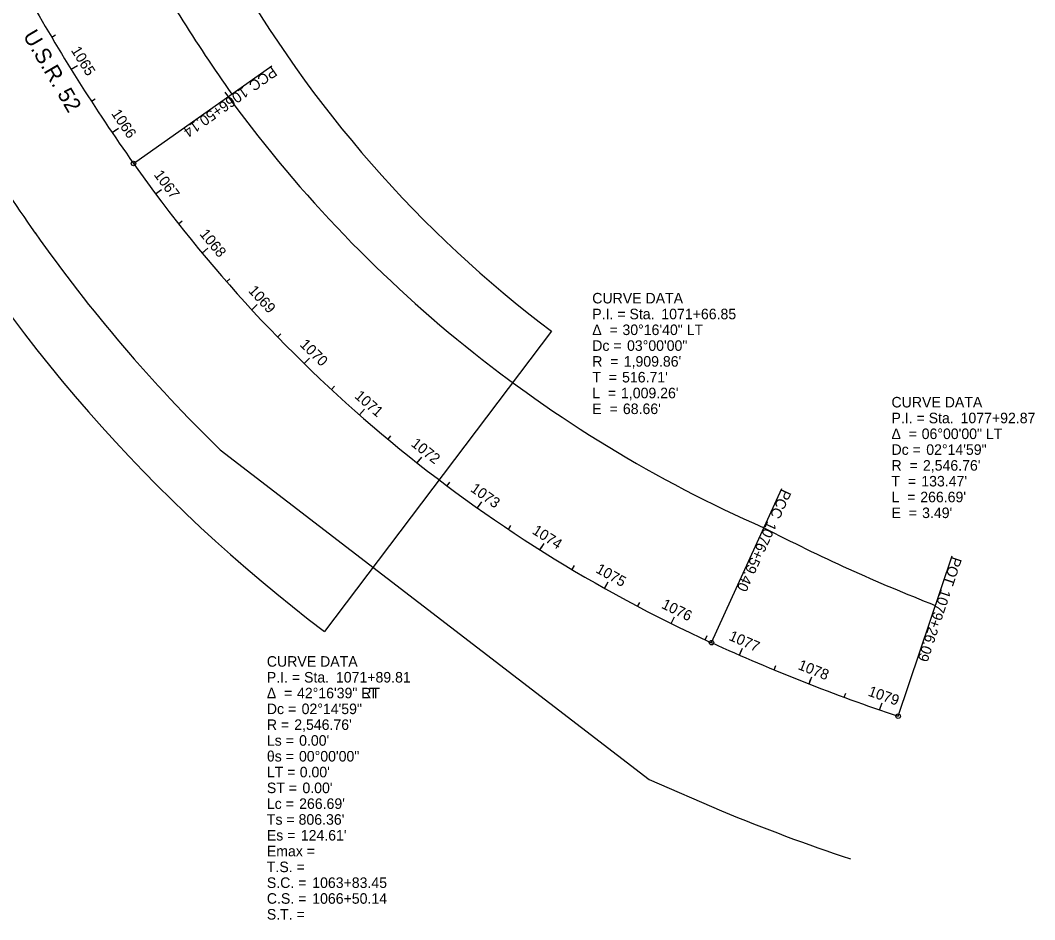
# Model space of a CAD drawing. Extents: x 1947854 to 1951648, y 150068 to 154534.
# Drawn here: x 1948658 to 1950006, y 151140 to 152335 of the extents above; entities that cross this region are included whole.
import ezdxf

# ---------------------------------------------------------------- set-up
doc = ezdxf.new("R2010")
doc.units = 0
for name, color, linetype in [('DR_X_Cells', 7, 'Continuous'), ('DR_X_Elev_Flow', 7, 'Continuous'), ('GE_X_Alignment', 7, 'Continuous'), ('GE_X_Alignment_100_Curve_Data', 7, 'Continuous'), ('RW_X_Esmt_LA', 7, 'Continuous'), ('SC_Scratch1', 7, 'Continuous'), ('SN_X_Public', 7, 'Continuous'), ('SV_P_Control_Cells_Set', 7, 'Continuous'), ('SV_X_Random_Point', 7, 'Continuous')]:
    doc.layers.add(name, color=color, linetype=linetype)

msp = doc.modelspace()

# ---------------------------------------------------------------- linework, layer by layer
at = {"layer": 'DR_X_Elev_Flow'}
for p, q in [((1948725.4, 152270.2), (1948730.5, 152273.3)), ((1948808.3, 152145), (1948992.2, 152274.7)), ((1949035, 151879.1), (1949042, 151886.3)), ((1949576.3, 151508.4), (1949669.7, 151713.1)), ((1949824.3, 151410.6), (1949895.8, 151623.9)), ((1949434.2, 151580.5), (1949437.2, 151585.7))]:
    msp.add_line(p, q, dxfattribs=at)
for centre in [(1948808.3, 152145), (1949576.3, 151508.4), (1949824.3, 151410.6)]:
    msp.add_circle(centre, 3, dxfattribs=at)
at = {"layer": 'GE_X_Alignment'}
for centre, radius, start, end in [((1950889.3, 153613.1), 2546.8, 209.2034, 215.2032), ((1950368.9, 153246), 1909.9, 215.2032, 245.481), ((1950633.2, 153825.5), 2546.8, 245.481, 251.4809)]:
    msp.add_arc(centre, radius, start, end, dxfattribs=at)
at = {"layer": 'RW_X_Esmt_LA'}
for p, q in [((1948923.3, 151764.6), (1949493.3, 151326.4)), ((1949493.3, 151326.4), (1949589.5, 151284.7))]:
    msp.add_line(p, q, dxfattribs=at)
for centre, radius, start, end in [((1950889.3, 153613.1), 2386.8, 209.2034, 215.2032), ((1950889.3, 153613.1), 2706.8, 209.2034, 215.2032), ((1950349, 153263.5), 1749.9, 215.7927, 246.3078), ((1950368.9, 153246), 2069.9, 215.2032, 225.699), ((1950743.9, 153780.3), 2386.8, 242.6106, 248.6111), ((1950633.2, 153825.5), 2746.8, 247.6673, 251.4809)]:
    msp.add_arc(centre, radius, start, end, dxfattribs=at)
at = {"layer": 'SC_Scratch1'}
msp.add_line((1949363.5, 151922.1), (1949061.9, 151523.3), dxfattribs=at)
for radius in [1600, 2100]:
    msp.add_arc((1950328.6, 153198.2), radius, 209.4864, 232.9007, dxfattribs=at)
at = {"layer": 'SN_X_Public'}
for p, q in [((1948699.5, 152312.9), (1948704.7, 152316)), ((1948725.4, 152270.2), (1948733.9, 152275.4)), ((1948808.3, 152145), (1948992.2, 152274.7)), ((1948752.2, 152227.9), (1948757.3, 152231.2)), ((1948779.8, 152186.2), (1948788.1, 152191.9)), ((1948808.3, 152145.1), (1948813.2, 152148.6)), ((1948837.6, 152104.6), (1948845.6, 152110.6)), ((1948868, 152064.9), (1948872.7, 152068.7)), ((1948899.4, 152026.1), (1948907.1, 152032.4)), ((1948931.9, 151988), (1948936.4, 151992)), ((1948965.3, 151950.8), (1948972.6, 151957.6)), ((1948999.7, 151914.5), (1949004, 151918.7)), ((1949035, 151879.1), (1949042, 151886.3)), ((1949071.2, 151844.7), (1949075.3, 151849.1)), ((1949108.4, 151811.2), (1949115, 151818.7)), ((1949146.4, 151778.7), (1949150.2, 151783.3)), ((1949185.2, 151747.2), (1949191.4, 151755)), ((1949224.8, 151716.7), (1949228.4, 151721.5)), ((1949576.3, 151508.4), (1949669.7, 151713.1)), ((1949265.2, 151687.3), (1949271, 151695.5)), ((1949306.4, 151658.9), (1949309.8, 151663.9)), ((1949348.3, 151631.7), (1949353.7, 151640.1)), ((1949824.3, 151410.6), (1949895.8, 151623.9)), ((1949390.9, 151605.5), (1949394, 151610.7)), ((1949434.2, 151580.5), (1949439.1, 151589.2)), ((1949478.1, 151556.6), (1949480.9, 151561.9)), ((1949522.7, 151533.8), (1949527.1, 151542.8)), ((1949567.8, 151512.3), (1949570.3, 151517.7)), ((1949613.4, 151491.8), (1949617.4, 151501)), ((1949659.4, 151472.2), (1949661.7, 151477.8)), ((1949705.8, 151453.6), (1949709.4, 151462.9)), ((1949752.5, 151435.8), (1949754.6, 151441.4)), ((1949799.6, 151419), (1949802.9, 151428.4))]:
    msp.add_line(p, q, dxfattribs=at)
for centre in [(1948808.3, 152145), (1949576.3, 151508.4), (1949824.3, 151410.6)]:
    msp.add_circle(centre, 3, dxfattribs=at)
at = {"layer": 'SV_X_Random_Point'}
for p, q in [((1948725.4, 152270.2), (1948733.9, 152275.4)), ((1948808.3, 152145), (1948992.2, 152274.7)), ((1948779.8, 152186.2), (1948784.8, 152189.6)), ((1948837.6, 152104.6), (1948842.4, 152108.2)), ((1948899.4, 152026.1), (1948904.1, 152029.9)), ((1948965.3, 151950.8), (1948969.7, 151954.9)), ((1949035, 151879.1), (1949042, 151886.3)), ((1949108.4, 151811.2), (1949112.3, 151815.7)), ((1949185.2, 151747.2), (1949188.9, 151751.9)), ((1949576.3, 151508.4), (1949669.7, 151713.1)), ((1949265.2, 151687.3), (1949268.7, 151692.2)), ((1949348.3, 151631.7), (1949351.5, 151636.7)), ((1949824.3, 151410.6), (1949895.8, 151623.9)), ((1949434.2, 151580.5), (1949439.1, 151589.2)), ((1949522.7, 151533.8), (1949525.3, 151539.2)), ((1949613.4, 151491.8), (1949615.8, 151497.3)), ((1949705.8, 151453.6), (1949708, 151459.2)), ((1949799.6, 151419), (1949801.6, 151424.7))]:
    msp.add_line(p, q, dxfattribs=at)
for centre in [(1948808.3, 152145), (1949576.3, 151508.4), (1949824.3, 151410.6)]:
    msp.add_circle(centre, 3, dxfattribs=at)

# ---------------------------------------------------------------- texts
at = {"layer": 'DR_X_Cells'}
for s, p in [('CURVE DATA', (1949417.8, 151959.1)), ('P.I. = Sta. ', (1949417.8, 151938.1)), ('1071+66.85', (1949509.6, 151938.1)), ('Δ  = ', (1949417.8, 151917.1)), ('30°16\'40" LT', (1949457.9, 151917.1)), ('Dc = ', (1949417.8, 151896.1)), ('03°00\'00"', (1949464, 151896.1)), ('R  = ', (1949417.8, 151875.1)), ("1,909.86'", (1949459.6, 151875.1)), ('T  = ', (1949417.8, 151854.1)), ("516.71'", (1949457.4, 151854.1)), ('L  = ', (1949417.8, 151833.1)), ("1,009.26'", (1949456, 151833.1)), ('CURVE DATA', (1949815.4, 151820.9)), ('E  = ', (1949417.8, 151812.1)), ("68.66'", (1949458.5, 151812.1)), ('P.I. = Sta. ', (1949815.4, 151799.9)), ('1077+92.87', (1949907.2, 151799.9)), ('Δ  = ', (1949815.4, 151778.9)), ('06°00\'00" LT', (1949855.5, 151778.9)), ('Dc = ', (1949815.4, 151757.9)), ('02°14\'59"', (1949861.6, 151757.9)), ('R  = ', (1949815.4, 151736.9)), ("2,546.76'", (1949857.2, 151736.9)), ('T  = ', (1949815.4, 151715.9)), ("133.47'", (1949855, 151715.9)), ('L  = ', (1949815.4, 151694.9)), ("266.69'", (1949853.6, 151694.9)), ('E  = ', (1949815.4, 151673.9)), ("3.49'", (1949856.1, 151673.9)), ('CURVE DATA', (1948985.4, 151476.4)), ('CURVE DATA', (1948985.4, 151476.4)), ('P.I. = Sta. ', (1948985.4, 151455.4)), ('P.I. = Sta. ', (1948985.4, 151455.4)), ('1071+89.81', (1949077.2, 151455.4)), ('1071+89.81', (1949077.2, 151455.4)), ('Δ  = ', (1948985.4, 151434.4)), ('Δ  = ', (1948985.4, 151434.4)), ('42°16\'39" LT', (1949025.5, 151434.4)), ('42°16\'39" RT', (1949025.5, 151434.4)), ('Dc = ', (1948985.4, 151413.4)), ('Dc = ', (1948985.4, 151413.4)), ('02°14\'59"', (1949031.6, 151413.4)), ('02°14\'59"', (1949031.6, 151413.4)), ('R = ', (1948985.4, 151392.4)), ('R = ', (1948985.4, 151392.4)), ("2,546.76'", (1949021.8, 151392.4)), ("2,546.76'", (1949021.8, 151392.4)), ('Ls = ', (1948985.4, 151371.4)), ('Ls = ', (1948985.4, 151371.4)), ("0.00'", (1949028.3, 151371.4)), ("0.00'", (1949028.3, 151371.4)), ('θs = ', (1948985.4, 151350.4)), ('θs = ', (1948985.4, 151350.4)), ('00°00\'00"', (1949028.1, 151350.4)), ('00°00\'00"', (1949028.1, 151350.4)), ('LT = ', (1948985.4, 151329.4)), ('LT = ', (1948985.4, 151329.4)), ("0.00'", (1949029.1, 151329.4)), ("0.00'", (1949029.1, 151329.4)), ('ST = ', (1948985.4, 151308.4)), ('ST = ', (1948985.4, 151308.4)), ("0.00'", (1949032.7, 151308.4)), ("0.00'", (1949032.7, 151308.4)), ('Lc = ', (1948985.4, 151287.4)), ('Lc = ', (1948985.4, 151287.4)), ("266.69'", (1949028.3, 151287.4)), ("266.69'", (1949028.3, 151287.4)), ('Ts = ', (1948985.4, 151266.4)), ('Ts = ', (1948985.4, 151266.4)), ("806.36'", (1949027.6, 151266.4)), ("806.36'", (1949027.6, 151266.4)), ('Es = ', (1948985.4, 151245.4)), ('Es = ', (1948985.4, 151245.4)), ("124.61'", (1949030.5, 151245.4)), ("124.61'", (1949030.5, 151245.4)), ('Emax = ', (1948985.4, 151224.4)), ('Emax = ', (1948985.4, 151224.4)), ('T.S. = ', (1948985.4, 151203.4)), ('T.S. = ', (1948985.4, 151203.4)), ('S.C. = ', (1948985.4, 151182.4)), ('S.C. = ', (1948985.4, 151182.4)), ('1063+83.45', (1949045.7, 151182.4)), ('1063+83.45', (1949045.7, 151182.4)), ('C.S. = ', (1948985.4, 151161.4)), ('C.S. = ', (1948985.4, 151161.4)), ('1066+50.14', (1949045.7, 151161.4)), ('1066+50.14', (1949045.7, 151161.4)), ('S.T. = ', (1948985.4, 151140.4)), ('S.T. = ', (1948985.4, 151140.4))]:
    msp.add_text(s, height=14, dxfattribs=at).set_placement(p)
at = {"layer": 'DR_X_Elev_Flow'}
for s, rotation, p in [('PCC', 215.2032, (1948992.5, 152274.6)), ('1066+50.14', 215.2032, (1948954.3, 152247.7)), ('1070', 315.699, (1949028.3, 151903.5)), ('PCC', 245.481, (1949670.1, 151713.3)), ('1076+59.40', 245.481, (1949650.7, 151670.8)), ('POT', 251.4809, (1949895.9, 151623.6)), ('1079+26.09', 251.4809, (1949881.4, 151580.3))]:
    msp.add_text(s, height=14, rotation=rotation, dxfattribs=at).set_placement(p)
at = {"layer": 'GE_X_Alignment_100_Curve_Data'}
for s, p in [('CURVE DATA', (1949417.8, 151959.1)), ('P.I. = Sta. ', (1949417.8, 151938.1)), ('1071+66.85', (1949509.6, 151938.1)), ('Δ  = ', (1949417.8, 151917.1)), ('30°16\'40" LT', (1949457.9, 151917.1)), ('Dc = ', (1949417.8, 151896.1)), ('03°00\'00"', (1949464, 151896.1)), ('R  = ', (1949417.8, 151875.1)), ("1,909.86'", (1949459.6, 151875.1)), ('T  = ', (1949417.8, 151854.1)), ("516.71'", (1949457.4, 151854.1)), ('L  = ', (1949417.8, 151833.1)), ("1,009.26'", (1949456, 151833.1)), ('CURVE DATA', (1949815.4, 151820.9)), ('E  = ', (1949417.8, 151812.1)), ("68.66'", (1949458.5, 151812.1)), ('P.I. = Sta. ', (1949815.4, 151799.9)), ('1077+92.87', (1949907.2, 151799.9)), ('Δ  = ', (1949815.4, 151778.9)), ('06°00\'00" LT', (1949855.5, 151778.9)), ('Dc = ', (1949815.4, 151757.9)), ('02°14\'59"', (1949861.6, 151757.9)), ('R  = ', (1949815.4, 151736.9)), ("2,546.76'", (1949857.2, 151736.9)), ('T  = ', (1949815.4, 151715.9)), ("133.47'", (1949855, 151715.9)), ('L  = ', (1949815.4, 151694.9)), ("266.69'", (1949853.6, 151694.9)), ('E  = ', (1949815.4, 151673.9)), ("3.49'", (1949856.1, 151673.9)), ('CURVE DATA', (1948985.4, 151476.4)), ('CURVE DATA', (1948985.4, 151476.4)), ('P.I. = Sta. ', (1948985.4, 151455.4)), ('P.I. = Sta. ', (1948985.4, 151455.4)), ('1071+89.81', (1949077.2, 151455.4)), ('1071+89.81', (1949077.2, 151455.4)), ('Δ  = ', (1948985.4, 151434.4)), ('Δ  = ', (1948985.4, 151434.4)), ('42°16\'39" LT', (1949025.5, 151434.4)), ('42°16\'39" RT', (1949025.5, 151434.4)), ('Dc = ', (1948985.4, 151413.4)), ('Dc = ', (1948985.4, 151413.4)), ('02°14\'59"', (1949031.6, 151413.4)), ('02°14\'59"', (1949031.6, 151413.4)), ('R = ', (1948985.4, 151392.4)), ('R = ', (1948985.4, 151392.4)), ("2,546.76'", (1949021.8, 151392.4)), ("2,546.76'", (1949021.8, 151392.4)), ('Ls = ', (1948985.4, 151371.4)), ('Ls = ', (1948985.4, 151371.4)), ("0.00'", (1949028.3, 151371.4)), ("0.00'", (1949028.3, 151371.4)), ('θs = ', (1948985.4, 151350.4)), ('θs = ', (1948985.4, 151350.4)), ('00°00\'00"', (1949028.1, 151350.4)), ('00°00\'00"', (1949028.1, 151350.4)), ('LT = ', (1948985.4, 151329.4)), ('LT = ', (1948985.4, 151329.4)), ("0.00'", (1949029.1, 151329.4)), ("0.00'", (1949029.1, 151329.4)), ('ST = ', (1948985.4, 151308.4)), ('ST = ', (1948985.4, 151308.4)), ("0.00'", (1949032.7, 151308.4)), ("0.00'", (1949032.7, 151308.4)), ('Lc = ', (1948985.4, 151287.4)), ('Lc = ', (1948985.4, 151287.4)), ("266.69'", (1949028.3, 151287.4)), ("266.69'", (1949028.3, 151287.4)), ('Ts = ', (1948985.4, 151266.4)), ('Ts = ', (1948985.4, 151266.4)), ("806.36'", (1949027.6, 151266.4)), ("806.36'", (1949027.6, 151266.4)), ('Es = ', (1948985.4, 151245.4)), ('Es = ', (1948985.4, 151245.4)), ("124.61'", (1949030.5, 151245.4)), ("124.61'", (1949030.5, 151245.4)), ('Emax = ', (1948985.4, 151224.4)), ('Emax = ', (1948985.4, 151224.4)), ('T.S. = ', (1948985.4, 151203.4)), ('T.S. = ', (1948985.4, 151203.4)), ('S.C. = ', (1948985.4, 151182.4)), ('S.C. = ', (1948985.4, 151182.4)), ('1063+83.45', (1949045.7, 151182.4)), ('1063+83.45', (1949045.7, 151182.4)), ('C.S. = ', (1948985.4, 151161.4)), ('C.S. = ', (1948985.4, 151161.4)), ('1066+50.14', (1949045.7, 151161.4)), ('1066+50.14', (1949045.7, 151161.4)), ('S.T. = ', (1948985.4, 151140.4)), ('S.T. = ', (1948985.4, 151140.4))]:
    msp.add_text(s, height=14, dxfattribs=at).set_placement(p)
at = {"layer": 'SC_Scratch1'}
msp.add_text('U.S.R. 52', height=20.83, rotation=300.4897, dxfattribs=at).set_placement((1948660.8, 152315))
at = {"layer": 'SN_X_Public'}
for s, rotation, p in [('1065', 301.8255, (1948724.7, 152295.5)), ('PCC', 215.2032, (1948992.5, 152274.6)), ('1066+50.14', 215.2032, (1948954.3, 152247.7)), ('1066', 304.0752, (1948778.1, 152211.5)), ('1067', 306.699, (1948834.6, 152130)), ('1068', 309.699, (1948895.3, 152051)), ('1069', 312.699, (1948959.9, 151975.4)), ('1070', 315.699, (1949028.3, 151903.5)), ('1071', 318.699, (1949101, 151834.6)), ('1072', 321.699, (1949176, 151770.7)), ('1073', 324.699, (1949254.9, 151710.3)), ('PCC', 245.481, (1949670.1, 151713.3)), ('1076+59.40', 245.481, (1949650.7, 151670.8)), ('1074', 327.699, (1949336.9, 151654)), ('1075', 330.699, (1949421.4, 151602.3)), ('POT', 251.4809, (1949895.9, 151623.6)), ('1079+26.09', 251.4809, (1949881.4, 151580.3)), ('1076', 333.699, (1949508.7, 151554.9)), ('1077', 336.3944, (1949598.2, 151512.3)), ('1078', 338.6442, (1949690.1, 151473.4)), ('1079', 340.8939, (1949783.3, 151438.1))]:
    msp.add_text(s, height=14, rotation=rotation, dxfattribs=at).set_placement(p)
at = {"layer": 'SV_P_Control_Cells_Set'}
for s, p in [('CURVE DATA', (1949417.8, 151959.1)), ('P.I. = Sta. ', (1949417.8, 151938.1)), ('1071+66.85', (1949509.6, 151938.1)), ('Δ  = ', (1949417.8, 151917.1)), ('30°16\'40" LT', (1949457.9, 151917.1)), ('Dc = ', (1949417.8, 151896.1)), ('03°00\'00"', (1949464, 151896.1)), ('R  = ', (1949417.8, 151875.1)), ("1,909.86'", (1949459.6, 151875.1)), ('T  = ', (1949417.8, 151854.1)), ("516.71'", (1949457.4, 151854.1)), ('L  = ', (1949417.8, 151833.1)), ("1,009.26'", (1949456, 151833.1)), ('CURVE DATA', (1949815.4, 151820.9)), ('E  = ', (1949417.8, 151812.1)), ("68.66'", (1949458.5, 151812.1)), ('P.I. = Sta. ', (1949815.4, 151799.9)), ('1077+92.87', (1949907.2, 151799.9)), ('Δ  = ', (1949815.4, 151778.9)), ('06°00\'00" LT', (1949855.5, 151778.9)), ('Dc = ', (1949815.4, 151757.9)), ('02°14\'59"', (1949861.6, 151757.9)), ('R  = ', (1949815.4, 151736.9)), ("2,546.76'", (1949857.2, 151736.9)), ('T  = ', (1949815.4, 151715.9)), ("133.47'", (1949855, 151715.9)), ('L  = ', (1949815.4, 151694.9)), ("266.69'", (1949853.6, 151694.9)), ('E  = ', (1949815.4, 151673.9)), ("3.49'", (1949856.1, 151673.9)), ('CURVE DATA', (1948985.4, 151476.4)), ('CURVE DATA', (1948985.4, 151476.4)), ('P.I. = Sta. ', (1948985.4, 151455.4)), ('P.I. = Sta. ', (1948985.4, 151455.4)), ('1071+89.81', (1949077.2, 151455.4)), ('1071+89.81', (1949077.2, 151455.4)), ('Δ  = ', (1948985.4, 151434.4)), ('Δ  = ', (1948985.4, 151434.4)), ('42°16\'39" LT', (1949025.5, 151434.4)), ('42°16\'39" RT', (1949025.5, 151434.4)), ('Dc = ', (1948985.4, 151413.4)), ('Dc = ', (1948985.4, 151413.4)), ('02°14\'59"', (1949031.6, 151413.4)), ('02°14\'59"', (1949031.6, 151413.4)), ('R = ', (1948985.4, 151392.4)), ('R = ', (1948985.4, 151392.4)), ("2,546.76'", (1949021.8, 151392.4)), ("2,546.76'", (1949021.8, 151392.4)), ('Ls = ', (1948985.4, 151371.4)), ('Ls = ', (1948985.4, 151371.4)), ("0.00'", (1949028.3, 151371.4)), ("0.00'", (1949028.3, 151371.4)), ('θs = ', (1948985.4, 151350.4)), ('θs = ', (1948985.4, 151350.4)), ('00°00\'00"', (1949028.1, 151350.4)), ('00°00\'00"', (1949028.1, 151350.4)), ('LT = ', (1948985.4, 151329.4)), ('LT = ', (1948985.4, 151329.4)), ("0.00'", (1949029.1, 151329.4)), ("0.00'", (1949029.1, 151329.4)), ('ST = ', (1948985.4, 151308.4)), ('ST = ', (1948985.4, 151308.4)), ("0.00'", (1949032.7, 151308.4)), ("0.00'", (1949032.7, 151308.4)), ('Lc = ', (1948985.4, 151287.4)), ('Lc = ', (1948985.4, 151287.4)), ("266.69'", (1949028.3, 151287.4)), ("266.69'", (1949028.3, 151287.4)), ('Ts = ', (1948985.4, 151266.4)), ('Ts = ', (1948985.4, 151266.4)), ("806.36'", (1949027.6, 151266.4)), ("806.36'", (1949027.6, 151266.4)), ('Es = ', (1948985.4, 151245.4)), ('Es = ', (1948985.4, 151245.4)), ("124.61'", (1949030.5, 151245.4)), ("124.61'", (1949030.5, 151245.4)), ('Emax = ', (1948985.4, 151224.4)), ('Emax = ', (1948985.4, 151224.4)), ('T.S. = ', (1948985.4, 151203.4)), ('T.S. = ', (1948985.4, 151203.4)), ('S.C. = ', (1948985.4, 151182.4)), ('S.C. = ', (1948985.4, 151182.4)), ('1063+83.45', (1949045.7, 151182.4)), ('1063+83.45', (1949045.7, 151182.4)), ('C.S. = ', (1948985.4, 151161.4)), ('C.S. = ', (1948985.4, 151161.4)), ('1066+50.14', (1949045.7, 151161.4)), ('1066+50.14', (1949045.7, 151161.4)), ('S.T. = ', (1948985.4, 151140.4)), ('S.T. = ', (1948985.4, 151140.4))]:
    msp.add_text(s, height=14, dxfattribs=at).set_placement(p)
at = {"layer": 'SV_X_Random_Point'}
for s, rotation, p in [('1065', 301.8255, (1948724.7, 152295.5)), ('PCC', 215.2032, (1948992.5, 152274.6)), ('1066+50.14', 215.2032, (1948954.3, 152247.7)), ('1070', 315.699, (1949028.3, 151903.5)), ('PCC', 245.481, (1949670.1, 151713.3)), ('1076+59.40', 245.481, (1949650.7, 151670.8)), ('1075', 330.699, (1949421.4, 151602.3)), ('POT', 251.4809, (1949895.9, 151623.6)), ('1079+26.09', 251.4809, (1949881.4, 151580.3))]:
    msp.add_text(s, height=14, rotation=rotation, dxfattribs=at).set_placement(p)

doc.saveas('drawing.dxf')
